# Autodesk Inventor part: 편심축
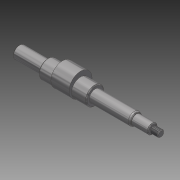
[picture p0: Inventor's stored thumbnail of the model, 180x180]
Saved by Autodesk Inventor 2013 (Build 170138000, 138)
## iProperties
Created: 2015-09
Part Number: 편심축
Material: 강철, 연강
Document SubType Name: Modeling
Designer: mduedu
Density: 1 g/cm^3
Author: mduedu
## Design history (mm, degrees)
sketch "스케치1"
  geometry: L1 (-87.5, 0)-(87.5, 0); L2 (-87.5, 0)-(-87.5, 7.5); L3 (-87.5, 7.5)-(-52.5, 7.5); L4 (-52.5, 7.5)-(-52.5, 11); L5 (-52.5, 11)-(5.5, 11); L6 (5.5, 11)-(5.5, 7.5); L7 (5.5, 7.5)-(53.855, 7.5); L8 (55.5, 6.55)-(55.5, 6); L9 (55.5, 6)-(75.5, 6); L10 (75.5, 6)-(75.5, 3); L11 (75.5, 3)-(76.5, 3); L12 (76.5, 3)-(76.5, 4); L13 (76.5, 4)-(87.5, 4); L14 (87.5, 4)-(87.5, 0); L15 (55.5, 6.55)-(53.855, 7.5); 2 further points
  constraints: 30 end point, 10 parallel, 2 perpendicular, 1 coincident, 1 collinear, 1 horizontal, 1 midpoint
  dimensions: "d0" = 35 distance of L2.end L3.end; "d2" = 58 distance of L4.end L5.end; "d4" = 175 distance of L1.start L1.end; "d5" = 20 distance of L8.end L9.end; "d6" = 1 distance of L10.end L11.end; "d7" = 8 diameter of L13 L1; "d8" = 6 diameter of L11 L1; "d9" = 12 diameter of L9 L1; "d10" = 15 diameter of L7 L1; "d11" = 22 diameter of L5 L1; "d12" = 15 diameter of L3 L1; "d40" = 13.1 diameter of L8.start L1; "d41" = 30 deg angle of L7 L15; "d43" = 50 distance between parallel lines of L8 L6
revolve "회전1" sketch "스케치1" stored, may be unused: angle "d13" = 90 deg
node "작업 평면1"
sketch "스케치3"
  geometry: C1 r 11 at (0, 0) reference; C2 r 14 at (0, 3); 1 further point
  constraints: 1 centre point, 1 tangent, 1 vertical alignment
  dimensions: "d19" = 28 diameter of C2
extrude "돌출1" join sketch "스케치3" stored distance "d21" = 22; taper "d22" = 0 deg
node "작업 평면2"
sketch "스케치4"
  geometry: L1 (10, 6.55)-(10, -6.55) reference; L2 (-10, 6)-(-10, -6) reference; L3 (10, 0)-(-10, 0); L4 (-5, -2)-(3, -2); L5 (3, 2)-(-5, 2); A1 r 2 centre (3, 0) between (3, -2) and (3, 2); A2 r 2 centre (-5, 0) between (-5, 2) and (-5, -2); 1 further point
  constraints: 6 end point, 4 point on circle, 4 tangent, 2 centre point, 2 midpoint, 2 parallel, 1 point on line
  dimensions: "d23" = 4 distance between parallel lines of L5 L4; "d25" = 12 dimension on A2 A1; "d26" = 3 distance edge to line of A2 L2
extrude "돌출2" cut sketch "스케치4" distance "d27" = 2.5; taper "d28" = 0 deg
chamfer "모따기1" distance "d29" = 1; stored, may be unused: second distance "d30" = 2, angle "d31" = 45 deg
feature "스레드1" dims "d32" = 10, "d33" = 0
chamfer "모따기2" distance "d34" = 1; stored, may be unused: second distance "d35" = 2, angle "d36" = 45 deg
chamfer "모따기3" distance "d37" = 1; stored, may be unused: second distance "d38" = 2, angle "d39" = 45 deg
fillet "모깎기1" dims "d42" = 4
node "솔리드1"
